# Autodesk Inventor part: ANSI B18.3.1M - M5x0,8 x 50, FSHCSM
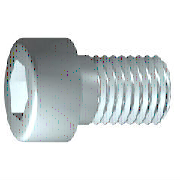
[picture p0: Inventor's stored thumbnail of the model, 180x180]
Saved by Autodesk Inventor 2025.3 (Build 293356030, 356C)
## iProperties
Created: 2024-01
Part Number: ANSI B18.3.1M - M5x0,8 x 50, FSHCSM
Material: Acciaio, Dolce
Description: Vite forgiata a testa incassata - Metrico
Document SubType Name: Modeling
Standard: ANSI B18.3.1M
Designer: R5800u
Standard Revision: 1979
Standards Organization: ANSI
Language: it-IT
Size Designation: M5x0,8 x 50
Categories: <MemberInstance><Categories><Category DisplayName="Elementi di fissaggio" InternalName="e4da775c-781d-43d5-af7c-5136215cf5a6" Mnemonic="FSTN"><Category DisplayN
Density: 7.85 g/cm^3
Appearance: Semilucidato
IsCustomPart: 0
Author: R5800u
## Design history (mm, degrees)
body "Solid1"
workplane "Work Plane1"
fillet "Fillet2" dims "d30" = 0.1 (= R)
revolve "Corpo" stored, may be unused: angle "d10" = 90 deg
sketch "Schizzo2"
  geometry: L1 (0, -5.95)-(0, 5.95) reference; L2 (-5.95, 0)-(5.95, 0) reference; L3 (2.309, 0)-(1.155, -2); L4 (1.155, -2)-(-1.155, -2); L5 (-1.155, -2)-(-2.309, 0); L6 (-2.309, 0)-(-1.155, 2); L7 (-1.155, 2)-(1.155, 2); L8 (1.155, 2)-(2.309, 0); 2 further points
  constraints: 12 end point, 1 coincident, 1 horizontal alignment, 1 point on line, 12 other
extrude "Intaglio" join sketch "Schizzo2" stored distance "d11" = 10; taper "d12" = 0 deg
fillet "Raccordo1" dims "d17" = 0.5 (= RR)
feature "Filettatura" dims "d13" = 22 (= GEL), "d14" = 0
chamfer "Smusso1" distance "d15" = 0.49076 (= -0.5 x SPD + 0.5 x GD); stored, may be unused: second distance "d16" = 0.49076 (= GUL), angle "d27" = 45 deg
sketch "Schizzo1"
  geometry: L1 (-1.167, 0)-(50, 0); L2 (50, 0)-(50, 2.5); L3 (50, 2.5)-(28, 2.5); L4 (28, 2.5)-(27.509, 2.5); L5 (27.509, 2.5)-(0, 2.5); L6 (0, 2.5)-(0, 4.25); L7 (0, 4.25)-(-5, 4.25); L8 (-5, 4.25)-(-5, 2.309); L9 (-5, 2.309)-(-2.5, 2.309); L10 (-2.5, 2.309)-(-1.167, 0); L11 (-16, 0)-(61, 0) reference; L12 (0, -0.85)-(0, 5.1) reference; L13 (28, 2.5)-(0, 2.5)
  constraints: 22 end point, 6 parallel, 2 collinear, 2 perpendicular, 1 horizontal, 1 point on line
  dimensions: "d1" = 22 distance from line of L3.end L2 (= GEL); "d2" = 0.49086 distance of L4.end L3.end (computed from GAL); "d3" = 5 distance between parallel lines of L8 L6 (= KOH); "d4" = 2.5 distance of L8.end L9.end (= INTI); "d5" = 60 deg angle of L10 L1; "d6" = 5 diameter of L3 L1 (= GD); "d7" = 5 diameter of L5 L1 (= BDM); "d8" = 4.6188 diameter of L9 L1 (= 1.1547 x SW); "d9" = 8.5 diameter of L7 L1 (= KOD); "d26" = 50 distance between parallel lines of L12 L2 (= NLG)
other parameters: "GD" = 5 (= NND) [user parameter; used in 2 equation terms], "NLG" = 50 [user parameter; used in 1 equation term], "GEL" = 22 [user parameter; used in 2 equation terms], "KOD" = 8.5 [user parameter; used in 1 equation term], "KOH" = 5 [user parameter; used in 1 equation term], "INTI" = 2.5 [user parameter; used in 1 equation term], "GAL" = 0.49076 (= 0.61345 x PTC) [user parameter; used in 1 equation term], "GUL" = 0.49076 (= 0.61345 x PTC) [user parameter; used in 1 equation term], "BDM" = 5 (= NND) [user parameter; used in 1 equation term], "SW" = 4 [user parameter; used in 2 equation terms], "RR" = 0.5 [user parameter; used in 1 equation term], "SPD" = 4.01848 [user parameter; used in 1 equation term], "d19" = 0, "d28" = 0, "d29" = 0, "R" = 0.1 [user parameter; used in 1 equation term], "TOA" = 30 deg [user parameter], "THREADDIA" = 5 [user parameter; used in 1 equation term], "TPU" = 12.5 (computed from PTC) [user parameter], "PTC" = 0.8 [user parameter; used in 4 equation terms], "NND" = 5 [user parameter; used in 2 equation terms], "E0" = 4.62 (= 1.155 x SW) [user parameter], "GD1" = 4.01848 (= THREADDIA - 1.2269 x PTC) [user parameter]
